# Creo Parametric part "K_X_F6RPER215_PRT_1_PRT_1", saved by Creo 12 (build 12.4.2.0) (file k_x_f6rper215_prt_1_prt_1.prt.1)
Units: Custom; MM, KILOGRAM, SECS

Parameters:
  PTC_WM_ITERATION = "0"
  PTC_WM_VERSION = "-.0"
  PTC_WM_LIFECYCLE_STATE = "In Work"
  PTC_WM_LIFECYCLE = "MO_CADDocument"
  PTC_WM_CREATED_BY = "Maximilian Roepper (Z0017RMS: MO)"
  PTC_WM_CREATED_ON = "18-Sep-26 11:36:42 AM"
  PTC_WM_MODIFIED_BY = "Maximilian Roepper (Z0017RMS: MO)"
  PTC_WM_MODIFIED_ON = "18-Sep-26 11:36:46 AM"
  PDMLINKNUMBER = "PDM000071454815"
  PTC_WM_NAME = "k_x_f6rper215_prt_1_prt_1.prt"
  PTC_WM_NUMBER = "PDM000071454815"

Other parameters: WEIGHT, WEIGHT_FACTOR, WEIGHT_ADD, _MASS_TEMP, _DIFF_TEMP, MC_ERRORS, SUPPLIER

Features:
  1. coordinate system
  2. datum plane "PRT_YZ"
  3. datum plane "PRT_XY"
  4. datum plane "PRT_XZ"
  5. coordinate system
  6. datum axis
  7. datum axis
  8. datum axis
  9. coordinate system
  10. imported feature
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
Other named items: PRT, SIEMENS_MO, DRW_VIEW_ORG, PRT_X, PRT_Y, PRT_Z, CS0, ROUGH_GROB

Layers: 00_STD_CSYS-KSYS, 01_STD_PLANES-EBENEN, 02_STD_AXES-ACHSEN, 03_STD_CSYS-KSYS, 24_IMPORT_FEAT-IMPORT_KE

Surfaces: 10 plane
